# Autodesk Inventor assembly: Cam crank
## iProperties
Created: 2008-07
Part Number: Cam crank
Document SubType Name: Assembly
Designer: tangg
Mass: 210.04 g
Surface Area: 145.642 cm^2
Volume: 32.7079 cm^3
Density: 6.4217 g/cm^3
Author: tangg
